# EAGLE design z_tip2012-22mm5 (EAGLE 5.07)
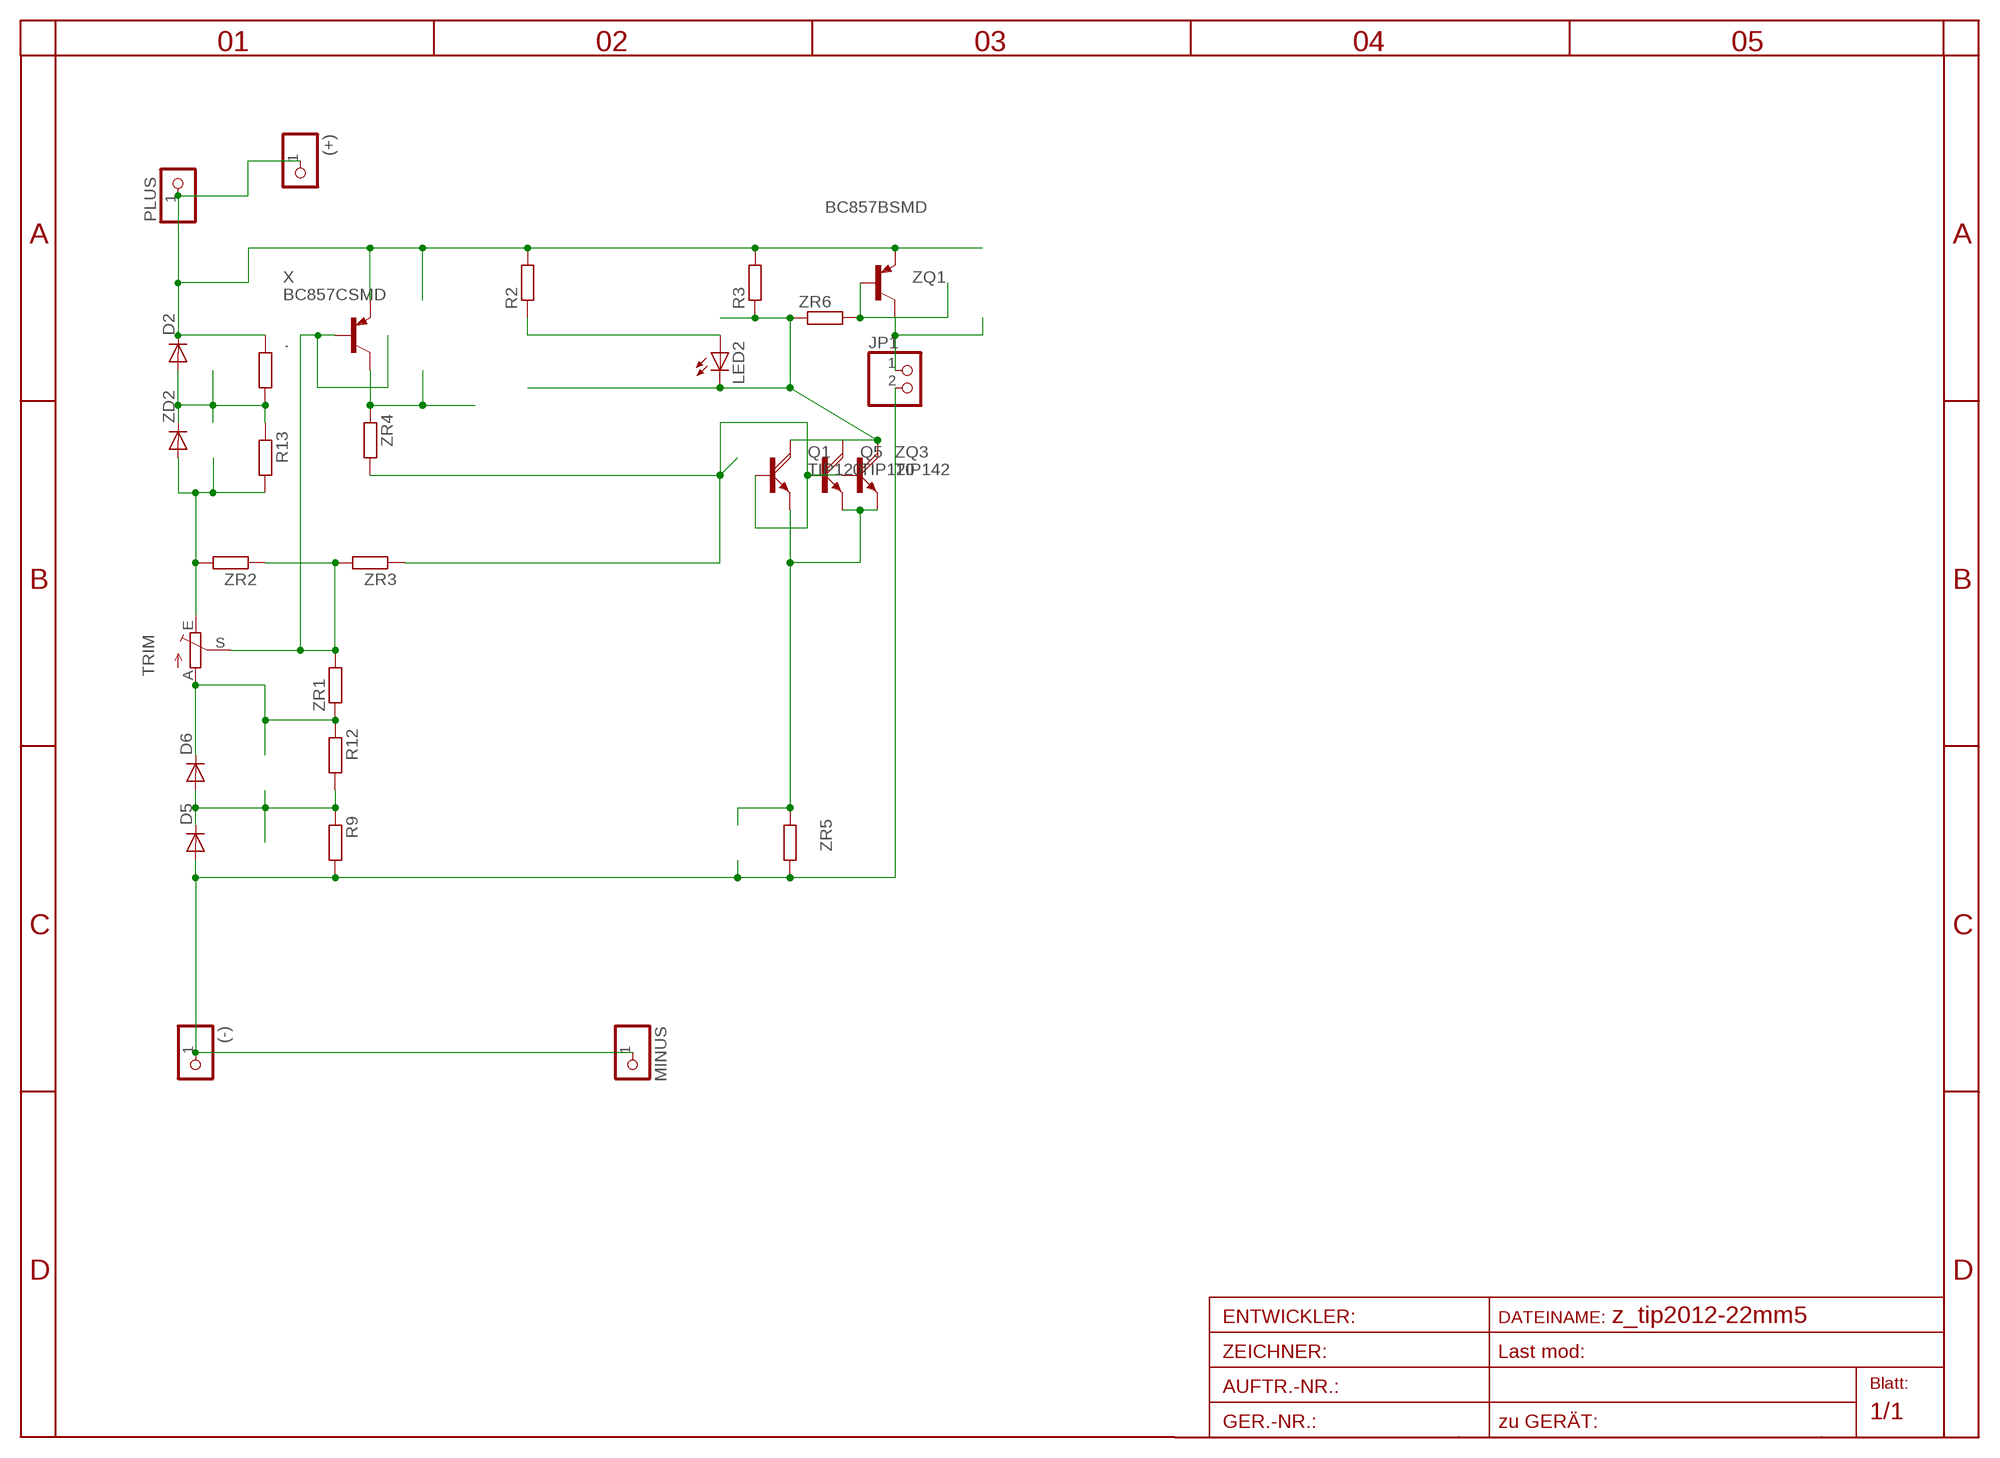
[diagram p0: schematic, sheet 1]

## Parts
(+)  PINHD-1X11MM6  [1X1MM8]
(-)  PINHD-1X11MM6  [1X1MM8]
.  R-EU_R0805  [R0805]
D2  DIODE-MINIMELF  [MINIMELF]
D5  DIODE-MINIMELF  [MINIMELF]
D6  DIODE-MINIMELF  [MINIMELF]
JP1  PINHD-1X2  [1X02]
LED2  LEDCHIPLED_1206  [CHIPLED_1206]
MINUS  PINHD-1X14.5MM  [1X4MM5]
PLUS  PINHD-1X14.5MM  [1X4MM5]
Q1  TIP120  TIP120DPAK  [D-PAK_TO252AA]
Q5  TIP120  TIP120TO220V  [TO220AV]
R2  R-EU_R1206  [R1206]
R3  R-EU_CERAM55  [CERAM55]
R9  R-EU_R0805  [R0805]
R12  R-EU_R0805  [R0805]
R13  R-EU_R0805  [R0805]
TRIM  TRIM_EU-S64W  [S64W]
X  BC857CSMD  [SOT23-BEC]
ZD2  DIODE-MINIMELF  [MINIMELF]
ZQ1  BC857BSMD  [SOT23-BEC]
ZQ3  TIP142  TIP142SOT93V  [SOT93V]
ZR1  R-EU_R0805  [R0805]
ZR2  R-EU_R0805  [R0805]
ZR3  R-EU_R0805  [R0805]
ZR4  R-EU_R1206  [R1206]
ZR5  R-EU_0617/22  [0617/22]
ZR6  R-EU_R1206  [R1206]

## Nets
B: TRIM.S X.B ZR1.2 ZR2.1 ZR3.2
C: LED2.C Q1.4(C) Q5.C R3.1 ZQ3.C ZR6.1
E: Q1.3(E) Q5.E ZQ3.E ZR5.2
G: Q1.1(B) Q5.B ZQ3.B ZR3.1 ZR4.2
MINUS: (-).1 D5.A JP1.2 MINUS.1 R9.2 ZR5.1
N$1: R13.2 TRIM.E ZD2.A ZR2.2
N$3: D5.C D6.A R9.1 R12.2
N$4: D6.C R12.1 TRIM.A ZR1.1
N$5: ..2 D2.A R13.1 ZD2.C
N$6: LED2.A R2.1
N$8: X.C ZR4.1
N$9: ZQ1.B ZR6.2
N$12: JP1.1 ZQ1.C
PLUS: (+).1 ..1 D2.C PLUS.1 R2.2 R3.2 X.E ZQ1.E

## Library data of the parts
(+) (-) MINUS PLUS = pinhead:PINHD-1X1: PIN HEADER
. R2 R3 R9 R12 R13 ZR1-ZR6 = rcl:R-EU_: RESISTOR, European symbol
D2 D5 D6 ZD2 = diode-1:DIODE-: DIODE
JP1 = pinhead:PINHD-1X2: PIN HEADER
LED2 = led:LED: LED
Q1 Q5 = transistor-power:TIP120: NPN DARLINGTON TRANSISTOR
TRIM = pot:TRIM_EU-: POTENTIOMETER
X ZQ1 = transistor-pnp:BC857*: PNP Transistror
ZQ3 = transistor-power:TIP142: NPN DARLINGTON TRANSISTOR

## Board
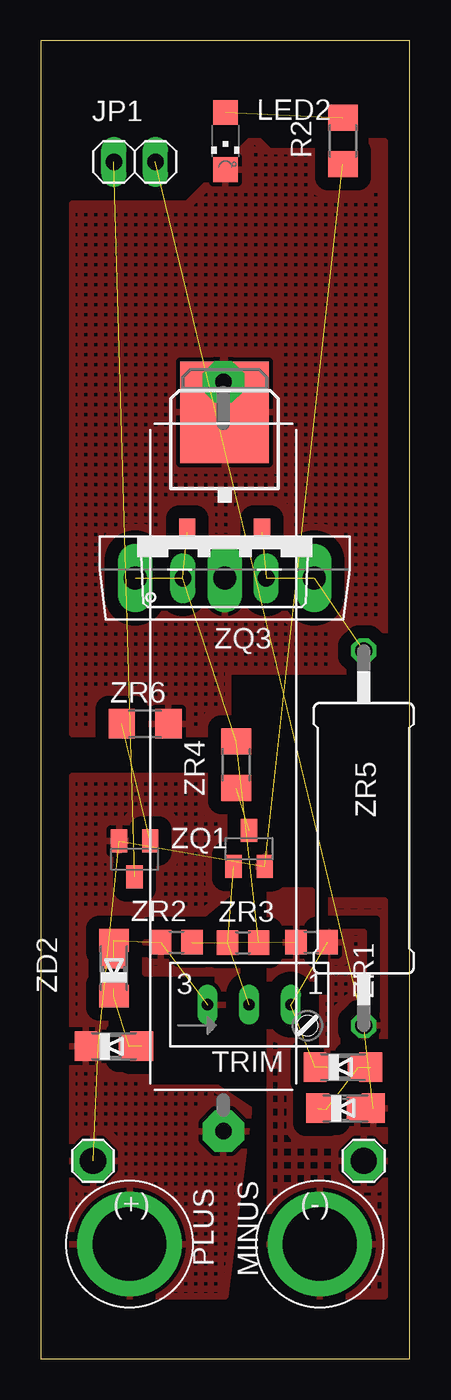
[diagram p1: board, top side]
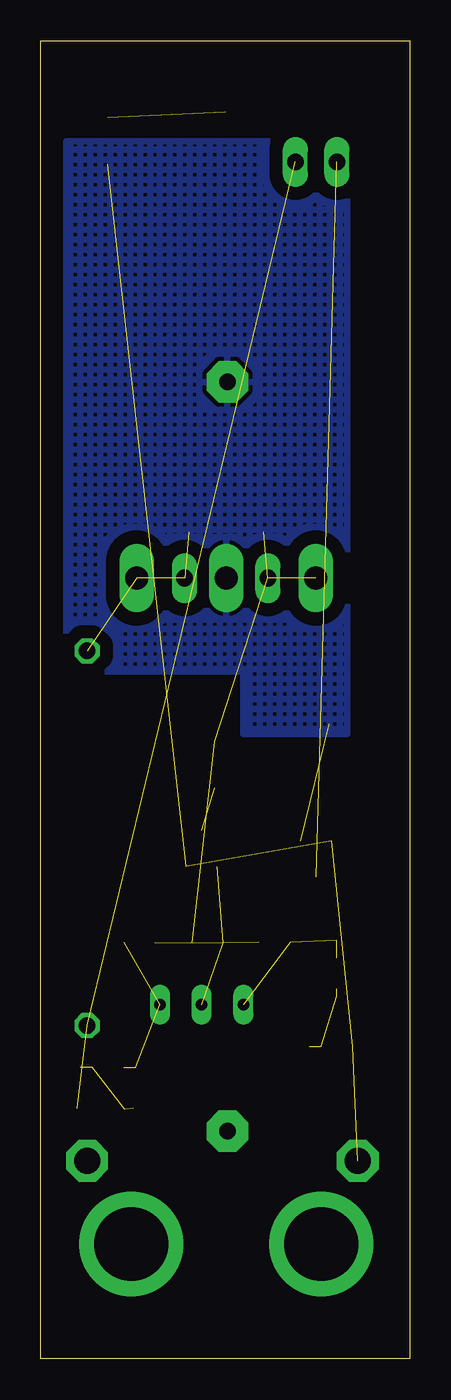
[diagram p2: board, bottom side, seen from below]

Size 22.5 x 80.4 mm. Coordinates in mm from the lower left corner, seen from the top.
Outline: 0,0 22.5,0 22.5,80.4 0,80.4 0,0
Copper layers (1*16): Top 0.035mm / dielectric 1.5mm / Bottom 0.035mm
Design rules "default": minimum track width 10mil, minimum drill 24mil, track to track 8mil, track to pad 8mil, pad to pad 8mil, via to via 8mil, smd to smd 8mil, copper to edge 40mil, drill to drill 8mil, minimum pad ring 10mil, minimum via ring 8mil, stop-mask expansion 4mil, vias tented up to drill 0mil, thermal gap 10mil

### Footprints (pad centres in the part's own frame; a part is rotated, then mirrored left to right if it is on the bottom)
1X1MM8 = drill 1.6 pad 2.54 octagon: 1 0,0
R0805 = smd 1.3 x 1.5: 1 -0.95,0; 2 0.95,0
MINIMELF = smd 1.4 x 1.8: A 1.7,0; C -1.7,0
1X02 = drill 1.016 long: 1 -1.27,0; 2 1.27,0
CHIPLED_1206 = smd 1.5 x 1.5: A 0,-1.75; C 0,1.75
1X4MM5 = drill 4.5 pad 6.35 round: 1 0,0
D-PAK_TO252AA = smd 1 x 1.6: 1 -2.28,-4.8; 3 2.28,-4.8 | smd 5.4 x 6.2: 4 0,2.5
TO220AV = drill 1.016 long: B -2.54,-2.54; C 0,-2.54; E 2.54,-2.54
R1206 = smd 1.6 x 1.803: 1 -1.422,0; 2 1.422,0
CERAM55 = drill 1 pad 2.54 octagon: 1 -22.86,0; 2 22.86,0
S64W = drill 0.7 long: A 2.54,1.27; E -2.54,1.27; S 0,1.27
SOT23-BEC = smd 1 x 1.4: B -0.95,-1.1; C 0,1.1; E 0.95,-1.1
SOT93V = drill 1.397 long: B -5.461,-2.54; C 0,-2.54; E 5.461,-2.54
0617/22 = drill 1.016 octagon: 1 -11.43,0; 2 11.43,0

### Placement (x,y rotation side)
(+)  3.17,12.06 0 top
(-)  19.68,12.06 0 top
.  4.45,19.05 0 top
D2  4.45,19.05 0 top
D5  18.58,15.27 0 top
D6  18.41,17.78 0 top
JP1  5.71,73.03 0 top
LED2  11.25,74.3 180 top
MINUS  17,6.99 0 top
PLUS  5.4,6.99 0 top
Q1  11.2,55.24 0 top
Q5  11.2,50.16 0 top
R2  18.41,74.3 270 top
R3  11.12,36.73 270 top
R9  18.34,15.21 0 top
R12  18.41,17.78 0 top
R13  4.45,23.5 90 top
TRIM  12.7,20.32 0 top
X  12.7,31.11 0 top
ZD2  4.45,23.81 90 top
ZQ1  5.71,30.48 180 top
ZQ3  11.2,50.16 0 top
ZR1  16.51,25.4 180 top
ZR2  8.26,25.4 180 top
ZR3  12.33,25.36 180 top
ZR4  11.91,36.23 90 top
ZR5  19.68,31.75 90 top
ZR6  6.35,38.73 180 top

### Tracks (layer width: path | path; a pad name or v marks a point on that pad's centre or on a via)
B  (4 unrouted)
  pour Top (isolate 0.813, rank 2): 13.97,28.57 13.97,17.14 16.51,17.14 16.51,28.57
C
  pour Bottom (isolate 0.813, rank 4, hatched): 20.95,41.91 10.16,41.91 10.16,38.1 3.81,38.1 3.81,74.3 20.95,74.3
  pour Top (isolate 0.813, rank 4, hatched): 20.95,41.91 11.43,41.91 11.43,38.1 1.91,38.1 1.91,70.48 8.89,70.48 12.7,74.3 13.34,74.3 13.97,73.66 16.51,73.66 17.14,74.3 20.95,74.3
E  (3 unrouted)
G  (4 unrouted)
MINUS  (2 unrouted)
  pour Top (isolate 0.813, rank 6, hatched): 13.97,27.94 20.95,27.94 20.95,3.81 13.97,3.81
N$1  (3 unrouted)
  pour Top (isolate 0.813, rank 3, hatched): 7.62,26.04 13.34,26.04 13.34,17.14 10.79,17.14 10.79,23.5 6.35,23.5 6.35,25.4
N$3  (3 unrouted)
N$4  (3 unrouted)
  pour Top (isolate 0.813, rank 3, hatched): 17.14,26.04 19.68,26.04 19.68,20.32 22.23,20.32 22.23,17.14 17.14,17.14
N$5  (3 unrouted)
N$6  (1 unrouted)
N$8  (1 unrouted)
N$9  (1 unrouted)
N$12  (1 unrouted)
PLUS  (4 unrouted)
  pour Top (isolate 0.813, rank 5, hatched): 1.91,35.56 13.97,35.56 13.97,30.48 6.35,24.13 6.35,16.51 10.79,16.51 12.7,15.24 11.25,3.81 1.91,3.81

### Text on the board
bTest: TIP122 | fuse | 1R8 10W | 101 | 202 | minus | plus | C..A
